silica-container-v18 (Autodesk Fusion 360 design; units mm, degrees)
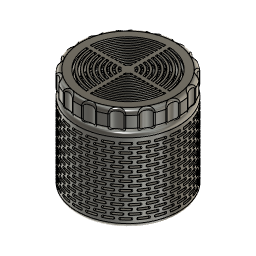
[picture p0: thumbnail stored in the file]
parameter "Spacing" = 1
parameter "Hole" = 1
sketch "Sketch1" plane through (0, 0, 0) normal (0, 0, 1) x axis (1, 0, 0)
  circle C1 centre (0, 0) radius 25
  circle C2 centre (0, 0) radius 23
  circle C3 centre (0, 0) radius 19
  circle C4 centre (0, 0) radius 24
  circle C5 centre (0, 0) radius 21
  point P1 (0, 0)
  point P2 (0, 0)
  point P5 (0, 0)
  coincident P1 P2
  concentric C1 C3
  coincident P1 P5
  concentric C4 C5
  dimension "d1" diameter C1 = 50
  dimension "d4" = -2
  dimension "d7" distance C2 C3 = 4
  dimension "d110" diameter C4 = 48
  dimension "d144" distance C2 C5 = 2
extrude "Extrude1" new body sketch "Sketch1" profile of C1 C2 C4 along normal blind 39
extrude "Extrude2" new body sketch "Sketch1" profile of C1 C2 C3 against normal blind 1.5
extrude "Extrude3" sketch "Sketch1" profile of C2 C5 blind -4
extrude "Extrude3" sketch "Sketch1" profile of C3 C5 blind 12 from offset -4
work_plane "WorkPlane3" AlongDistance 0
chamfer "Chamfer1" distance 4
split "Split4"
sketch "Bottom stuff" plane through (0, 0, 0) normal (0, 0, 1) x axis (-1, 0, 0)
  line L1 (1, -23.4787) -> (1, -1)
  line L2 (-1, -1) -> (-1, -23.4787)
  line L3 (-23.4787, -1) -> (-1, -1)
  line L4 (-1, 1) -> (-23.4787, 1)
  line L5 (-1, 23.4787) -> (-1, 1)
  line L6 (1, 1) -> (1, 23.4787)
  line L7 (23.4787, 1) -> (1, 1)
  line L8 (1, -1) -> (23.4787, -1)
  circle C1 centre (0, 0) radius 2.5
  circle C2 centre (0, 0) radius 3.5
  circle C3 centre (0, 0) radius 4.5
  circle C4 centre (0, 0) radius 3.5
  circle C5 centre (0, 0) radius 4.5
  circle C6 centre (0, 0) radius 5.5
  circle C7 centre (0, 0) radius 6.5
  circle C8 centre (0, 0) radius 7.5
  circle C9 centre (0, 0) radius 8.5
  circle C10 centre (0, 0) radius 9.5
  circle C11 centre (0, 0) radius 10.5
  circle C12 centre (0, 0) radius 11.5
  circle C13 centre (0, 0) radius 12.5
  circle C14 centre (0, 0) radius 13.5
  circle C15 centre (0, 0) radius 14.5
  circle C16 centre (0, 0) radius 15.5
  circle C17 centre (0, 0) radius 16.5
  circle C18 centre (0, 0) radius 17.5
  circle C19 centre (0, 0) radius 18.5
  circle C20 centre (0, 0) radius 19.5
  circle C21 centre (0, 0) radius 20.5
  circle C22 centre (0, 0) radius 21.5
  circle C23 centre (0, 0) radius 1.5
  circle C24 centre (0, 0) radius 25
  vertical L1
  parallel L1 L2
  perpendicular L1 L3
  perpendicular L1 L4
  perpendicular L4 L5
  perpendicular L4 L6
  perpendicular L5 L7
  perpendicular L1 L8
  concentric C1 C2
  concentric C1 C3
  concentric C4 C6
  concentric C1 C7
  concentric C4 C8
  concentric C7 C9
  concentric C9 C10
  concentric C7 C11
  concentric C2 C12
  concentric C6 C13
  concentric C7 C14
  concentric C2 C15
  concentric C2 C16
  concentric C2 C17
  concentric C2 C18
  concentric C2 C19
  concentric C19 C20
  concentric C19 C21
  concentric C2 C22
  concentric C6 C23
  collinear L3 L8
  collinear L4 L7
  collinear L1 L6
  collinear L2 L5
  equal L3 L8
  equal L1 L6
  dimension "d26" diameter C1 = 5
  dimension "d27" distance C1 C2 = 1 (= "Hole")
  dimension "d28" distance C2 C3 = 1 (= "Spacing")
  dimension "d30" distance C4 C5 = 1 (= "Spacing")
  dimension "d31" distance C3 C6 = 1 (= "Hole")
  dimension "d32" distance C6 C7 = 1 (= "Spacing")
  dimension "d33" distance C7 C8 = 1 (= "Hole")
  dimension "d34" distance C8 C9 = 1 (= "Spacing")
  dimension "d36" distance C9 C10 = 1 (= "Hole")
  dimension "d37" distance C10 C11 = 1 (= "Spacing")
  dimension "d38" distance C11 C12 = 1 (= "Hole")
  dimension "d39" distance C12 C13 = 1 (= "Spacing")
  dimension "d40" distance C13 C14 = 1 (= "Hole")
  dimension "d41" distance C14 C15 = 1 (= "Spacing")
  dimension "d42" distance C15 C16 = 1 (= "Hole")
  dimension "d43" distance C16 C17 = 1 (= "Spacing")
  dimension "d44" distance C17 C18 = 1 (= "Hole")
  dimension "d45" distance C18 C19 = 1 (= "Spacing")
  dimension "d46" distance C19 C20 = 1 (= "Hole")
  dimension "d47" distance C20 C21 = 1 (= "Spacing")
  dimension "d48" distance C21 C22 = 1 (= "Hole")
  dimension "d49" diameter C23 = 3
  dimension "d51" distance L7 L8 = 2
  dimension "d52" distance L1 L2 = 2
extrude "Extrude4" cut sketch "Bottom stuff" profile of L1 L2 L3 L4 L5 L6 L7 L8 C1 C2 C3 C4 C5 C6 C7 C8 C9 C10 C11 C12 C13 C14 C15 C16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 against normal blind 2
combine "Combine1"
chamfer "Chamfer2" distance 0.5
fillet "Fillet1" radius 2
work_plane "WorkPlane2" AlongDistance 0.5
split "Split2"
split "Split3" bodies "Container"
work_plane "WorkPlane4" RotateAngle 0
sketch "Holy hole" plane through (0, -25, 20.5391) normal (0, -1, 0) x axis (1, 0, 0)
  line L1 (0, -37.0783) -> (0, 0)
  line L2 (2, -17.5391) -> (-2, -17.5391)
  line L3 (2, -18.5391) -> (2, -17.5391)
  line L4 (-2, -18.5391) -> (2, -18.5391)
  line L5 (-2, -17.5391) -> (-2, -18.5391)
  line L6 (5.25, -15.5391) -> (1.25, -15.5391)
  line L7 (5.25, -16.5391) -> (5.25, -15.5391)
  line L8 (1.25, -16.5391) -> (5.25, -16.5391)
  line L9 (1.25, -15.5391) -> (1.25, -16.5391)
  line L10 (25, -20.0391) -> (-25, -20.0391)
  circle C1 centre (-2, -18.0391) radius 0.5
  circle C2 centre (2, -18.0391) radius 0.5
  circle C3 centre (1.25, -16.0391) radius 0.5
  circle C4 centre (5.25, -16.0391) radius 0.5
  point P1 (0, 0)
  point P2 (0, 0)
  point P4 (-2, -17.5391)
  point P7 (-2, -18.5391)
  point P6 (2, -18.5391)
  point P5 (2, -17.5391)
  point P10 (1.25, -15.5391)
  point P13 (1.25, -16.5391)
  point P11 (5.25, -15.5391)
  point P12 (5.25, -16.5391)
  point P14 (1.25, -16.0391)
  coincident P1 P2
  vertical L1
  horizontal L2
  vertical L3
  horizontal L4
  vertical L5
  coincident P4 C1
  tangent L2 C1
  coincident P7 C1
  coincident P6 C2
  tangent L4 C2
  coincident P5 C2
  midpoint L1 L4
  horizontal L6
  vertical L7
  horizontal L8
  vertical L9
  coincident P10 C3
  tangent L6 C3
  coincident P13 C3
  coincident P11 C4
  tangent L6 C4
  coincident P12 C4
  dimension "d80" distance P4 P5 = 4
  dimension "d81" distance L2 L4 = 1
  dimension "d82" distance P10 P11 = 4
  dimension "d83" distance P10 P13 = 1
  dimension "d84" distance L2 L8 = 1
  dimension "d95" distance L4 L10 = 1.5
  dimension "d169" distance L1 P14 = 1.25
emboss "Emboss1" sketch "Holy hole" Depth -2 Horizontal Distance 0 Vertical Distance 0 Rotation Angle 0
circular_pattern "C-Pattern2" countU 25 TotalAngle 360
rectangular_pattern "R-Pattern1" countU 21 uSpaceDistance 4 vSpaceDistance 0
extrude "Extrude1" sketch "Sketch1" profile of C2 C3 blind 1.5
extrude "Extrude2" sketch "Sketch1" profile of C1 C2 C4 blind -9.5
work_plane "WorkPlane5" AlongDistance -8
split "Split1"
thread "Thread2" ThreadOffset 1 ThreadLength 8
sketch "Sketch7" plane through (0, 0, 47) normal (0, 0, 1) x axis (-1, 0, 0)
  curve K1 (21.6609, -2.8687) -> (-2.7702, -20.9174)
  curve K2 (-19.5001, 8.0596) -> (8.3461, 20.1932)
  circle C1 centre (0, 0) radius 19
  circle C2 centre (0, 0) radius 21.85
  arc A1 centre (0, 0) radius 21.1 clockwise from (-2.7702, -20.9174) to (-19.5001, 8.0596)
  arc A2 centre (0, 0) radius 21.85 clockwise from (21.6609, -2.8687) to (8.3461, 20.1932)
  circle C3 centre (0, 0) radius 21.1
  concentric A1 C3
  tangent A1 C3
extrude "Extrude4" cut sketch "Sketch7" profile of C2 A1 C3 against normal blind 1
sketch "Cap holes" plane through (0, 0, 48.5) normal (0, 0, 1) x axis (-1, 0, 0)
  line L1 (1, 20.4756) -> (1, 21.4767)
  line L2 (21.4767, 1) -> (20.4756, 1)
  line L3 (1, 12.4599) -> (1, 13.4629)
  line L4 (13.4629, 1) -> (12.4599, 1)
  line L5 (18.473, -1) -> (19.4743, -1)
  line L6 (1, -19.4743) -> (1, -18.473)
  line L7 (10.4523, -1) -> (11.4564, -1)
  line L8 (1, -11.4564) -> (1, -10.4523)
  line L9 (-16.4697, 1) -> (-17.4714, 1)
  line L10 (-1, 17.4714) -> (-1, 16.4697)
  line L11 (-8.441, 1) -> (-9.4472, 1)
  line L12 (-1, 9.4472) -> (-1, 8.441)
  line L13 (-1, -14.4655) -> (-1, -15.4677)
  line L14 (-15.4677, -1) -> (-14.4655, -1)
  line L15 (-1, -6.4226) -> (-1, -7.433)
  line L16 (-7.433, -1) -> (-6.4226, -1)
  line L17 (-1, -4.3875) -> (-1, -5.4083)
  line L18 (-5.4083, -1) -> (-4.3875, -1)
  line L19 (-1, -2.2913) -> (-1, -3.3541)
  line L20 (-3.3541, -1) -> (-2.2913, -1)
  line L21 (1, 2.2913) -> (1, 3.3541)
  line L22 (3.3541, 1) -> (2.2913, 1)
  line L23 (1, 4.3875) -> (1, 5.4083)
  line L24 (5.4083, 1) -> (4.3875, 1)
  line L25 (1, 6.4226) -> (1, 7.433)
  line L26 (7.433, 1) -> (6.4226, 1)
  line L27 (-1, -8.441) -> (-1, -9.4472)
  line L28 (-9.4472, -1) -> (-8.441, -1)
  line L29 (-1, -16.4697) -> (-1, -17.4714)
  line L30 (-17.4714, -1) -> (-16.4697, -1)
  line L31 (-10.4523, 1) -> (-11.4564, 1)
  line L32 (-1, 11.4564) -> (-1, 10.4523)
  line L33 (-18.473, 1) -> (-19.4743, 1)
  line L34 (-1, 19.4743) -> (-1, 18.473)
  line L35 (12.4599, -1) -> (13.4629, -1)
  line L36 (1, -13.4629) -> (1, -12.4599)
  line L37 (20.4756, -1) -> (21.4767, -1)
  line L38 (1, -21.4767) -> (1, -20.4756)
  line L39 (1, 14.4655) -> (1, 15.4677)
  line L40 (15.4677, 1) -> (14.4655, 1)
  line L41 (1, 18.473) -> (1, 19.4743)
  line L42 (19.4743, 1) -> (18.473, 1)
  line L43 (1, 10.4523) -> (1, 11.4564)
  line L44 (11.4564, 1) -> (10.4523, 1)
  line L45 (16.4697, -1) -> (17.4714, -1)
  line L46 (1, -17.4714) -> (1, -16.4697)
  line L47 (8.441, -1) -> (9.4472, -1)
  line L48 (1, -9.4472) -> (1, -8.441)
  line L49 (-14.4655, 1) -> (-15.4677, 1)
  line L50 (-1, 15.4677) -> (-1, 14.4655)
  line L51 (-1, -20.4756) -> (-1, -21.4767)
  line L52 (-21.4767, -1) -> (-20.4756, -1)
  line L53 (-1, -12.4599) -> (-1, -13.4629)
  line L54 (-13.4629, -1) -> (-12.4599, -1)
  line L55 (-6.4226, 1) -> (-7.433, 1)
  line L56 (-1, 7.433) -> (-1, 6.4226)
  line L57 (-4.3875, 1) -> (-5.4083, 1)
  line L58 (-1, 5.4083) -> (-1, 4.3875)
  line L59 (-2.2913, 1) -> (-3.3541, 1)
  line L60 (-1, 3.3541) -> (-1, 2.2913)
  line L61 (2.2913, -1) -> (3.3541, -1)
  line L62 (1, -3.3541) -> (1, -2.2913)
  line L63 (4.3875, -1) -> (5.4083, -1)
  line L64 (1, -5.4083) -> (1, -4.3875)
  line L65 (6.4226, -1) -> (7.433, -1)
  line L66 (1, -7.433) -> (1, -6.4226)
  line L67 (-1, -10.4523) -> (-1, -11.4564)
  line L68 (-11.4564, -1) -> (-10.4523, -1)
  line L69 (-1, -18.473) -> (-1, -19.4743)
  line L70 (-19.4743, -1) -> (-18.473, -1)
  line L71 (-12.4599, 1) -> (-13.4629, 1)
  line L72 (-1, 13.4629) -> (-1, 12.4599)
  line L73 (-20.4756, 1) -> (-21.4767, 1)
  line L74 (-1, 21.4767) -> (-1, 20.4756)
  line L75 (14.4655, -1) -> (15.4677, -1)
  line L76 (1, -15.4677) -> (1, -14.4655)
  line L77 (1, 8.441) -> (1, 9.4472)
  line L78 (9.4472, 1) -> (8.441, 1)
  line L79 (1, 16.4697) -> (1, 17.4714)
  line L80 (17.4714, 1) -> (16.4697, 1)
  circle C1 centre (0, 0) radius 25
  arc A1 centre (0, 0) radius 21.5 clockwise from (1, 21.4767) to (21.4767, 1)
  arc A2 centre (0, 0) radius 20.5 clockwise from (1, 20.4756) to (20.4756, 1)
  arc A3 centre (0, 0) radius 13.5 clockwise from (1, 13.4629) to (13.4629, 1)
  arc A4 centre (0, 0) radius 12.5 clockwise from (1, 12.4599) to (12.4599, 1)
  arc A5 centre (0, 0) radius 19.5 clockwise from (19.4743, -1) to (1, -19.4743)
  arc A6 centre (0, 0) radius 18.5 clockwise from (18.473, -1) to (1, -18.473)
  arc A7 centre (0, 0) radius 11.5 clockwise from (11.4564, -1) to (1, -11.4564)
  arc A8 centre (0, 0) radius 10.5 clockwise from (10.4523, -1) to (1, -10.4523)
  arc A9 centre (0, 0) radius 17.5 clockwise from (-17.4714, 1) to (-1, 17.4714)
  arc A10 centre (0, 0) radius 16.5 clockwise from (-16.4697, 1) to (-1, 16.4697)
  arc A11 centre (0, 0) radius 9.5 clockwise from (-9.4472, 1) to (-1, 9.4472)
  arc A12 centre (0, 0) radius 8.5 clockwise from (-8.441, 1) to (-1, 8.441)
  arc A13 centre (0, 0) radius 15.5 clockwise from (-1, -15.4677) to (-15.4677, -1)
  arc A14 centre (0, 0) radius 14.5 clockwise from (-1, -14.4655) to (-14.4655, -1)
  arc A15 centre (0, 0) radius 7.5 clockwise from (-1, -7.433) to (-7.433, -1)
  arc A16 centre (0, 0) radius 6.5 clockwise from (-1, -6.4226) to (-6.4226, -1)
  arc A17 centre (0, 0) radius 5.5 clockwise from (-1, -5.4083) to (-5.4083, -1)
  arc A18 centre (0, 0) radius 4.5 clockwise from (-1, -4.3875) to (-4.3875, -1)
  arc A19 centre (0, 0) radius 3.5 clockwise from (-1, -3.3541) to (-3.3541, -1)
  arc A20 centre (0, 0) radius 2.5 clockwise from (-1, -2.2913) to (-2.2913, -1)
  arc A21 centre (0, 0) radius 3.5 clockwise from (1, 3.3541) to (3.3541, 1)
  arc A22 centre (0, 0) radius 2.5 clockwise from (1, 2.2913) to (2.2913, 1)
  arc A23 centre (0, 0) radius 5.5 clockwise from (1, 5.4083) to (5.4083, 1)
  arc A24 centre (0, 0) radius 4.5 clockwise from (1, 4.3875) to (4.3875, 1)
  arc A25 centre (0, 0) radius 7.5 clockwise from (1, 7.433) to (7.433, 1)
  arc A26 centre (0, 0) radius 6.5 clockwise from (1, 6.4226) to (6.4226, 1)
  arc A27 centre (0, 0) radius 9.5 clockwise from (-1, -9.4472) to (-9.4472, -1)
  arc A28 centre (0, 0) radius 8.5 clockwise from (-1, -8.441) to (-8.441, -1)
  arc A29 centre (0, 0) radius 17.5 clockwise from (-1, -17.4714) to (-17.4714, -1)
  arc A30 centre (0, 0) radius 16.5 clockwise from (-1, -16.4697) to (-16.4697, -1)
  arc A31 centre (0, 0) radius 11.5 clockwise from (-11.4564, 1) to (-1, 11.4564)
  arc A32 centre (0, 0) radius 10.5 clockwise from (-10.4523, 1) to (-1, 10.4523)
  arc A33 centre (0, 0) radius 19.5 clockwise from (-19.4743, 1) to (-1, 19.4743)
  arc A34 centre (0, 0) radius 18.5 clockwise from (-18.473, 1) to (-1, 18.473)
  arc A35 centre (0, 0) radius 13.5 clockwise from (13.4629, -1) to (1, -13.4629)
  arc A36 centre (0, 0) radius 12.5 clockwise from (12.4599, -1) to (1, -12.4599)
  arc A37 centre (0, 0) radius 21.5 clockwise from (21.4767, -1) to (1, -21.4767)
  arc A38 centre (0, 0) radius 20.5 clockwise from (20.4756, -1) to (1, -20.4756)
  arc A39 centre (0, 0) radius 15.5 clockwise from (1, 15.4677) to (15.4677, 1)
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extrude "Extrude4" cut sketch "Cap holes" to an object
thread "Thread2" ThreadOffset 1 ThreadLength 7
chamfer "Chamfer1" distance 0.5
fillet "Fillet1" radius 2
sketch "Knurls" plane through (0, 0, 48.5) normal (0, 0, 1) x axis (1, 0, 0)
  line L1 (0, 48.9451) -> (0, 0)
  line L2 (-1, -3.3541) -> (-1, -2.2913)
  line L3 (-2.2913, -1) -> (-3.3541, -1)
  line L4 (-1, -11.4564) -> (-1, -10.4523)
  line L5 (-10.4523, -1) -> (-11.4564, -1)
  line L6 (-1, -19.4743) -> (-1, -18.473)
  line L7 (-18.473, -1) -> (-19.4743, -1)
  line L8 (-13.4629, 1) -> (-12.4599, 1)
  line L9 (-1, 12.4599) -> (-1, 13.4629)
  line L10 (-5.4083, 1) -> (-4.3875, 1)
  line L11 (-1, 4.3875) -> (-1, 5.4083)
  line L12 (7.433, -1) -> (6.4226, -1)
  line L13 (1, -6.4226) -> (1, -7.433)
  line L14 (15.4677, -1) -> (14.4655, -1)
  line L15 (1, -14.4655) -> (1, -15.4677)
  line L16 (1, 17.4714) -> (1, 16.4697)
  line L17 (16.4697, 1) -> (17.4714, 1)
  line L18 (1, 9.4472) -> (1, 8.441)
  line L19 (8.441, 1) -> (9.4472, 1)
  line L20 (1, 3.3541) -> (1, 2.2913)
  line L21 (2.2913, 1) -> (3.3541, 1)
  line L22 (1, 11.4564) -> (1, 10.4523)
  line L23 (10.4523, 1) -> (11.4564, 1)
  line L24 (1, 19.4743) -> (1, 18.473)
  line L25 (18.473, 1) -> (19.4743, 1)
  line L26 (13.4629, -1) -> (12.4599, -1)
  line L27 (1, -12.4599) -> (1, -13.4629)
  line L28 (5.4083, -1) -> (4.3875, -1)
  line L29 (1, -4.3875) -> (1, -5.4083)
  line L30 (-7.433, 1) -> (-6.4226, 1)
  line L31 (-1, 6.4226) -> (-1, 7.433)
  line L32 (-15.4677, 1) -> (-14.4655, 1)
  line L33 (-1, 14.4655) -> (-1, 15.4677)
  line L34 (-1, -17.4714) -> (-1, -16.4697)
  line L35 (-16.4697, -1) -> (-17.4714, -1)
  line L36 (-1, -9.4472) -> (-1, -8.441)
  line L37 (-8.441, -1) -> (-9.4472, -1)
  line L38 (-1, -5.4083) -> (-1, -4.3875)
  line L39 (-4.3875, -1) -> (-5.4083, -1)
  line L40 (-1, -13.4629) -> (-1, -12.4599)
  line L41 (-12.4599, -1) -> (-13.4629, -1)
  line L42 (-19.4743, 1) -> (-18.473, 1)
  line L43 (-1, 18.473) -> (-1, 19.4743)
  line L44 (-11.4564, 1) -> (-10.4523, 1)
  line L45 (-1, 10.4523) -> (-1, 11.4564)
  line L46 (-3.3541, 1) -> (-2.2913, 1)
  line L47 (-1, 2.2913) -> (-1, 3.3541)
  line L48 (9.4472, -1) -> (8.441, -1)
  line L49 (1, -8.441) -> (1, -9.4472)
  line L50 (17.4714, -1) -> (16.4697, -1)
  line L51 (1, -16.4697) -> (1, -17.4714)
  line L52 (1, 15.4677) -> (1, 14.4655)
  line L53 (14.4655, 1) -> (15.4677, 1)
  line L54 (1, 7.433) -> (1, 6.4226)
  line L55 (6.4226, 1) -> (7.433, 1)
  line L56 (1, 5.4083) -> (1, 4.3875)
  line L57 (4.3875, 1) -> (5.4083, 1)
  line L58 (1, 13.4629) -> (1, 12.4599)
  line L59 (12.4599, 1) -> (13.4629, 1)
  line L60 (19.4743, -1) -> (18.473, -1)
  line L61 (1, -18.473) -> (1, -19.4743)
  line L62 (11.4564, -1) -> (10.4523, -1)
  line L63 (1, -10.4523) -> (1, -11.4564)
  line L64 (3.3541, -1) -> (2.2913, -1)
  line L65 (1, -2.2913) -> (1, -3.3541)
  line L66 (-9.4472, 1) -> (-8.441, 1)
  line L67 (-1, 8.441) -> (-1, 9.4472)
  line L68 (-17.4714, 1) -> (-16.4697, 1)
  line L69 (-1, 16.4697) -> (-1, 17.4714)
  line L70 (-1, -15.4677) -> (-1, -14.4655)
  line L71 (-14.4655, -1) -> (-15.4677, -1)
  line L72 (-1, -7.433) -> (-1, -6.4226)
  line L73 (-6.4226, -1) -> (-7.433, -1)
  circle C1 centre (0, 29) radius 5
  circle C2 centre (0, 0) radius 24
  circle C3 centre (0, 0) radius 23
  circle C4 centre (0, 0) radius 21
  arc A1 centre (0, 0) radius 2.5 clockwise from (-1, -2.2913) to (-2.2913, -1)
  arc A2 centre (0, 0) radius 3.5 clockwise from (-1, -3.3541) to (-3.3541, -1)
  arc A3 centre (0, 0) radius 10.5 clockwise from (-1, -10.4523) to (-10.4523, -1)
  arc A4 centre (0, 0) radius 11.5 clockwise from (-1, -11.4564) to (-11.4564, -1)
  arc A5 centre (0, 0) radius 18.5 clockwise from (-1, -18.473) to (-18.473, -1)
  arc A6 centre (0, 0) radius 19.5 clockwise from (-1, -19.4743) to (-19.4743, -1)
  arc A7 centre (0, 0) radius 12.5 clockwise from (-12.4599, 1) to (-1, 12.4599)
  arc A8 centre (0, 0) radius 13.5 clockwise from (-13.4629, 1) to (-1, 13.4629)
  arc A9 centre (0, 0) radius 4.5 clockwise from (-4.3875, 1) to (-1, 4.3875)
  arc A10 centre (0, 0) radius 5.5 clockwise from (-5.4083, 1) to (-1, 5.4083)
  arc A11 centre (0, 0) radius 6.5 clockwise from (6.4226, -1) to (1, -6.4226)
  arc A12 centre (0, 0) radius 7.5 clockwise from (7.433, -1) to (1, -7.433)
  arc A13 centre (0, 0) radius 14.5 clockwise from (14.4655, -1) to (1, -14.4655)
  arc A14 centre (0, 0) radius 15.5 clockwise from (15.4677, -1) to (1, -15.4677)
  arc A15 centre (0, 0) radius 16.5 clockwise from (1, 16.4697) to (16.4697, 1)
  arc A16 centre (0, 0) radius 17.5 clockwise from (1, 17.4714) to (17.4714, 1)
  arc A17 centre (0, 0) radius 8.5 clockwise from (1, 8.441) to (8.441, 1)
  arc A18 centre (0, 0) radius 9.5 clockwise from (1, 9.4472) to (9.4472, 1)
  arc A19 centre (0, 0) radius 2.5 clockwise from (1, 2.2913) to (2.2913, 1)
  arc A20 centre (0, 0) radius 3.5 clockwise from (1, 3.3541) to (3.3541, 1)
  arc A21 centre (0, 0) radius 10.5 clockwise from (1, 10.4523) to (10.4523, 1)
  arc A22 centre (0, 0) radius 11.5 clockwise from (1, 11.4564) to (11.4564, 1)
  arc A23 centre (0, 0) radius 18.5 clockwise from (1, 18.473) to (18.473, 1)
  arc A24 centre (0, 0) radius 19.5 clockwise from (1, 19.4743) to (19.4743, 1)
  arc A25 centre (0, 0) radius 12.5 clockwise from (12.4599, -1) to (1, -12.4599)
  arc A26 centre (0, 0) radius 13.5 clockwise from (13.4629, -1) to (1, -13.4629)
  arc A27 centre (0, 0) radius 4.5 clockwise from (4.3875, -1) to (1, -4.3875)
  arc A28 centre (0, 0) radius 5.5 clockwise from (5.4083, -1) to (1, -5.4083)
  arc A29 centre (0, 0) radius 6.5 clockwise from (-6.4226, 1) to (-1, 6.4226)
  arc A30 centre (0, 0) radius 7.5 clockwise from (-7.433, 1) to (-1, 7.433)
  arc A31 centre (0, 0) radius 14.5 clockwise from (-14.4655, 1) to (-1, 14.4655)
  arc A32 centre (0, 0) radius 15.5 clockwise from (-15.4677, 1) to (-1, 15.4677)
  arc A33 centre (0, 0) radius 16.5 clockwise from (-1, -16.4697) to (-16.4697, -1)
  arc A34 centre (0, 0) radius 17.5 clockwise from (-1, -17.4714) to (-17.4714, -1)
  arc A35 centre (0, 0) radius 8.5 clockwise from (-1, -8.441) to (-8.441, -1)
  arc A36 centre (0, 0) radius 9.5 clockwise from (-1, -9.4472) to (-9.4472, -1)
  arc A37 centre (0, 0) radius 4.5 clockwise from (-1, -4.3875) to (-4.3875, -1)
  arc A38 centre (0, 0) radius 5.5 clockwise from (-1, -5.4083) to (-5.4083, -1)
  arc A39 centre (0, 0) radius 12.5 clockwise from (-1, -12.4599) to (-12.4599, -1)
  arc A40 centre (0, 0) radius 13.5 clockwise from (-1, -13.4629) to (-13.4629, -1)
  arc A41 centre (0, 0) radius 18.5 clockwise from (-18.473, 1) to (-1, 18.473)
  arc A42 centre (0, 0) radius 19.5 clockwise from (-19.4743, 1) to (-1, 19.4743)
  arc A43 centre (0, 0) radius 10.5 clockwise from (-10.4523, 1) to (-1, 10.4523)
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  point P1 (0, 0)
  point P2 (0, 0)
  point P4 (0, 29)
  coincident P1 P2
  vertical L1
  coincident L1 P4
  tangent C1 C2
  dimension "d123" diameter C1 = 10
extrude "Extrude5" cut sketch "Knurls" profile of C1 blind -10
fillet "Fillet2" radius 1
circular_pattern "C-Pattern2" countU 15 TotalAngle 360
sketch "Sketch9" plane through (0, 0, 39) normal (0, 0, -1) x axis (1, 0, 0)
  curve K1 (-2.9081, -21.9583) -> (21.2148, -2.8096)
  curve K2 (8.1742, 19.7773) -> (-20.4705, 8.4607)
  circle C1 centre (0, 0) radius 21.4
  arc A1 centre (0, 0) radius 23 clockwise from (0, -23) to (-9.3549, -21.0115)
  arc A2 centre (0, 0) radius 23 clockwise from (9.3549, -21.0115) to (0, -23)
  arc A3 centre (0, 0) radius 23 clockwise from (17.0923, -15.39) to (9.3549, -21.0115)
  arc A4 centre (0, 0) radius 23 clockwise from (21.8743, -7.1074) to (17.0923, -15.39)
  arc A5 centre (0, 0) radius 23 clockwise from (22.874, 2.4042) to (21.8743, -7.1074)
  arc A6 centre (0, 0) radius 23 clockwise from (19.9186, 11.5) to (22.874, 2.4042)
  arc A7 centre (0, 0) radius 23 clockwise from (13.5191, 18.6074) to (19.9186, 11.5)
  arc A8 centre (0, 0) radius 23 clockwise from (4.782, 22.4974) to (13.5191, 18.6074)
  arc A9 centre (0, 0) radius 23 clockwise from (-4.782, 22.4974) to (4.782, 22.4974)
  arc A10 centre (0, 0) radius 23 clockwise from (-13.5191, 18.6074) to (-4.782, 22.4974)
  arc A11 centre (0, 0) radius 23 clockwise from (-19.9186, 11.5) to (-13.5191, 18.6074)
  arc A12 centre (0, 0) radius 23 clockwise from (-22.874, 2.4042) to (-19.9186, 11.5)
  arc A13 centre (0, 0) radius 23 clockwise from (-21.8743, -7.1074) to (-22.874, 2.4042)
  arc A14 centre (0, 0) radius 23 clockwise from (-17.0923, -15.39) to (-21.8743, -7.1074)
  arc A15 centre (0, 0) radius 23 clockwise from (-9.3549, -21.0115) to (-17.0923, -15.39)
  arc A16 centre (0, 0) radius 21.4 clockwise from (21.2148, -2.8096) to (8.1742, 19.7773)
  arc A17 centre (0, 0) radius 22.15 clockwise from (-2.9081, -21.9583) to (-20.4705, 8.4607)
extrude "Extrude6" cut sketch "Sketch9" profile of C1 A16 K1 A17 K2 against normal blind 1
joint "Assemble1" alignAngle 0 alignOffsetX 0 alignOffsetY 0 alignOffsetZ 0
combine "Combine1"
chamfer "Chamfer1" distance 0.5
chamfer "Chamfer2" distance 1
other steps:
create_component "CreateComponent1"
create_component "CreateComponent2"
joint_origin "JointOrigin3"
joint_origin "JointOrigin3"
named bodies: "Container", "Cap"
